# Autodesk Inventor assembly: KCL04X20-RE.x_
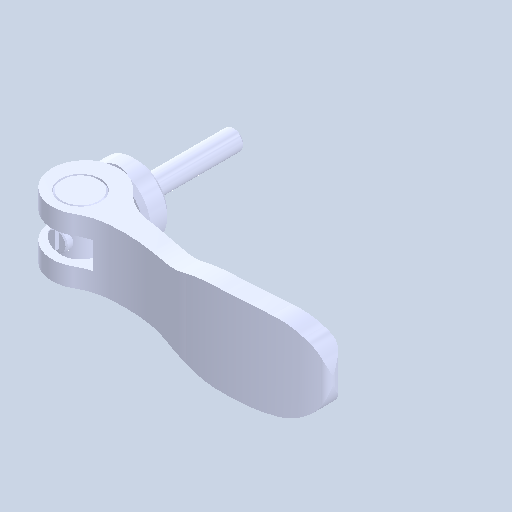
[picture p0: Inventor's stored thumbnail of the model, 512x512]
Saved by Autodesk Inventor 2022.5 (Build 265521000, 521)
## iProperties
Created: 2024-08
Part Number: KCL04X20-RE.x_
Document SubType Name: Assembly
Designer: ImaoCorp
Author: ImaoCorp
Sending System: SOLIDWORKS 2022-2022290
MC: AMD64
MC_MODEL: Intel64 Family 6 Model 60 Stepping 3, GenuineIntel
OS: Windows_NT
FRU: Parasolid Version 33.1, build 260,  4-25-2022
FORMAT: text
GUISE: transmit
KEY: FILEKCL04X20-RE.x_t
DATE: Thu Aug 29 10:47:54 2024
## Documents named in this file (5)
- Y:\5.更新分\2024年対応\1001_KCL\データ\kcl04x20-re\KCL04X20-RE.x_.iam
- Y:\5.更新分\2024年対応\1001_KCL\データ\kcl04x20-re\KCL4X20-RE_01.ipt
- Y:\5.更新分\2024年対応\1001_KCL\データ\kcl04x20-re\KCL4X20-RE_02.ipt
- Y:\5.更新分\2024年対応\1001_KCL\データ\kcl04x20-re\KCL4X20-RE_03.ipt
- Y:\5.更新分\2024年対応\1001_KCL\データ\kcl04x20-re\KCL4X20-RE_04.ipt
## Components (4 placed, 4 different names)
1. KCL4X20-RE_01
2. KCL4X20-RE_02
3. KCL4X20-RE_03
4. KCL4X20-RE_04
